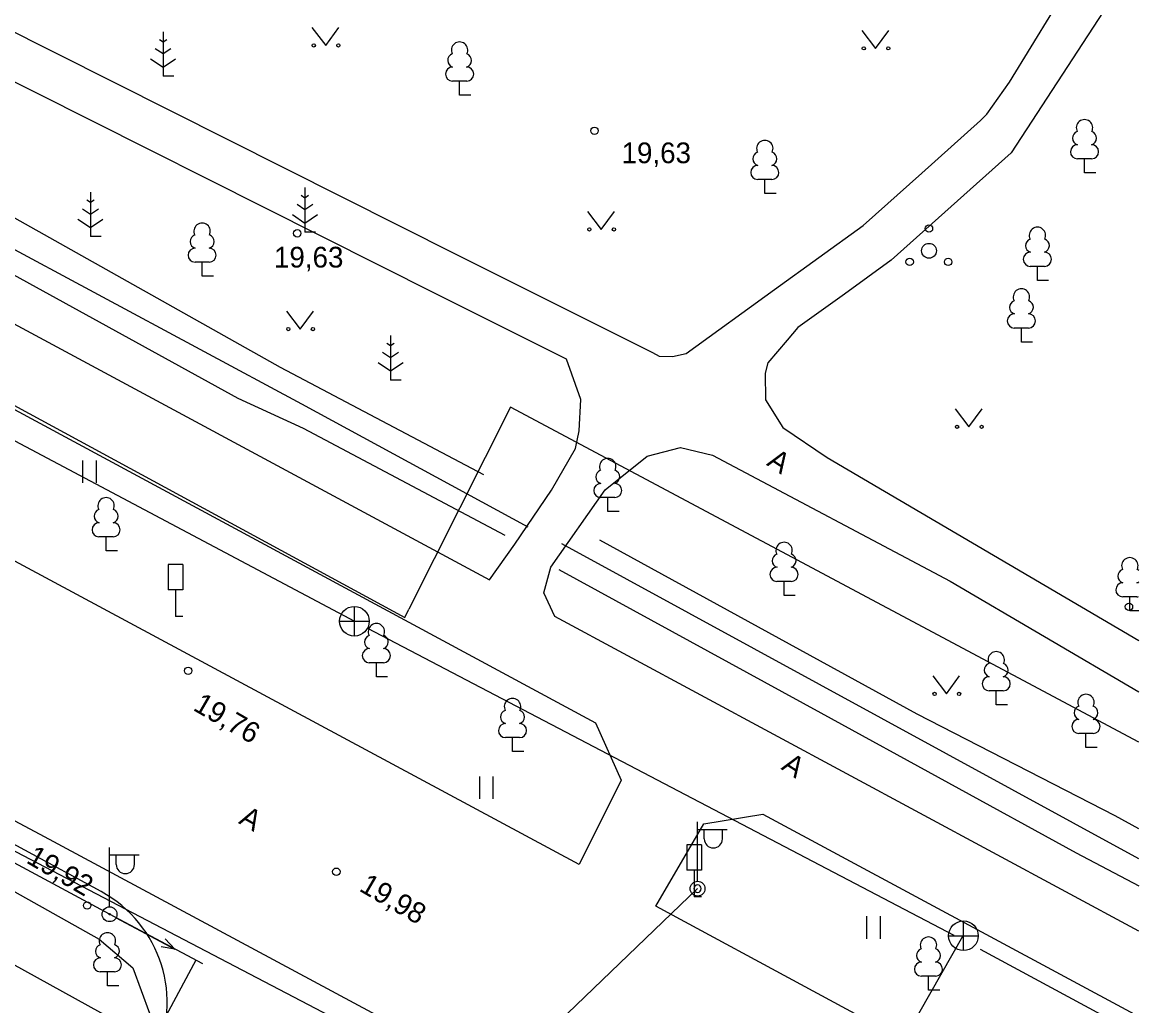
# Model space of a CAD drawing. Extents: x 713497 to 713863, y 6590062 to 6590327.
# Drawn here: x 713825.68 to 713863.36, y 6590124.29 to 6590157.47 of the extents above; entities that cross this region are included whole.
import ezdxf

# ---------------------------------------------------------------- set-up
doc = ezdxf.new("R2010")
doc.units = 0
for name, color, linetype in [('AED', 7, 'Continuous'), ('HALJASTUS', 7, 'Continuous'), ('HOONE', 7, 'Continuous'), ('KKAEV', 7, 'Continuous'), ('KORGUS', 7, 'Continuous'), ('KTRASS', 7, 'Continuous'), ('LIIKLUS', 7, 'Continuous'), ('MPKAABEL', 7, 'Continuous'), ('MPOHULIIN', 7, 'Continuous'), ('POST', 7, 'Continuous'), ('PUU', 7, 'Continuous'), ('SITRASS', 7, 'Continuous'), ('TEE', 7, 'Continuous'), ('TTRASS', 7, 'Continuous'), ('VTRASS', 7, 'Continuous')]:
    doc.layers.add(name, color=color, linetype=linetype)

msp = doc.modelspace()

# ---------------------------------------------------------------- linework, layer by layer
at = {"layer": 'AED'}
for points in [[(713842.75, 6590140.44), (713835.11, 6590144.59), (713824.81, 6590150.12), (713803.9, 6590161.43), (713731.96, 6590199.96)], [(713863.358, 6590129.245), (713843.89, 6590139.87)]]:
    msp.add_lwpolyline(points, dxfattribs=at)
at = {"layer": 'HALJASTUS'}
for p, q in [((713835.457, 6590157.297), (713835.92, 6590156.69)), ((713835.92, 6590156.69), (713836.366, 6590157.297)), ((713854.017, 6590157.197), (713854.48, 6590156.59)), ((713854.48, 6590156.59), (713854.926, 6590157.197)), ((713844.757, 6590151.087), (713845.22, 6590150.48)), ((713845.22, 6590150.48), (713845.666, 6590151.087)), ((713834.597, 6590147.727), (713835.06, 6590147.12)), ((713835.06, 6590147.12), (713835.506, 6590147.727)), ((713857.167, 6590144.427), (713857.63, 6590143.82)), ((713857.63, 6590143.82), (713858.076, 6590144.427)), ((713827.715, 6590142.688), (713827.715, 6590141.927)), ((713828.17, 6590142.688), (713828.17, 6590141.927)), ((713856.407, 6590135.417), (713856.87, 6590134.81)), ((713856.87, 6590134.81), (713857.316, 6590135.417)), ((713841.11, 6590132.026), (713841.11, 6590131.264)), ((713841.565, 6590132.026), (713841.565, 6590131.264)), ((713854.176, 6590127.307), (713854.176, 6590126.546)), ((713854.631, 6590127.307), (713854.631, 6590126.546))]:
    msp.add_line(p, q, dxfattribs=at)
for points in [[(713841.26, 6590142.2), (713834.39, 6590145.82), (713823.52, 6590151.93), (713808.23, 6590160.2), (713806.22, 6590161.53), (713798.4, 6590165.35), (713781.9, 6590174.22), (713774.18, 6590178.32), (713771.41, 6590180.04), (713767.95, 6590181.54), (713761.08, 6590185.35), (713755.64, 6590188.21), (713751.36, 6590190.34), (713748.73, 6590191.96), (713741.58, 6590196.11), (713734, 6590200.4)], [(713732.19, 6590199.21), (713738.7, 6590195.69), (713747.61, 6590190.82), (713767.02, 6590180.35), (713771.65, 6590178.11), (713786.98, 6590169.69), (713793.79, 6590166.16), (713813.16, 6590155.69), (713817.55, 6590153.26), (713832.96, 6590144.79), (713835.16, 6590143.78), (713841.97, 6590140.16)], [(713863.358, 6590130.259), (713862.56, 6590130.7), (713855.88, 6590134.13), (713845.17, 6590140)], [(713843.79, 6590139.01), (713852.63, 6590134.17), (713861.25, 6590129.45), (713863.358, 6590128.329)]]:
    msp.add_lwpolyline(points, dxfattribs=at)
for centre, radius in [((713835.519, 6590156.69), 0.055), ((713836.348, 6590156.69), 0.055), ((713854.079, 6590156.59), 0.055), ((713854.908, 6590156.59), 0.055), ((713844.819, 6590150.48), 0.055), ((713845.648, 6590150.48), 0.055), ((713856.28, 6590150.51), 0.125), ((713856.28, 6590149.76), 0.25), ((713855.63, 6590149.385), 0.125), ((713856.93, 6590149.385), 0.125), ((713834.659, 6590147.12), 0.055), ((713835.488, 6590147.12), 0.055), ((713857.229, 6590143.82), 0.055), ((713858.058, 6590143.82), 0.055), ((713856.469, 6590134.81), 0.055), ((713857.298, 6590134.81), 0.055)]:
    msp.add_circle(centre, radius, dxfattribs=at)
at = {"layer": 'HOONE'}
msp.add_lwpolyline([(713734.713, 6590179.152), (713785.66, 6590151.72), (713826.27, 6590130.08), (713863.358, 6590110.159)], dxfattribs=at)
at = {"layer": 'KKAEV'}
for p, q in [((713836.888, 6590136.76), (713836.888, 6590137.76)), ((713836.388, 6590137.26), (713837.388, 6590137.26)), ((713857.445, 6590126.148), (713857.445, 6590127.148)), ((713856.945, 6590126.648), (713857.945, 6590126.648))]:
    msp.add_line(p, q, dxfattribs=at)
for centre in [(713836.888, 6590137.26), (713857.445, 6590126.648)]:
    msp.add_circle(centre, 0.5, dxfattribs=at)
at = {"layer": 'KORGUS'}
for centre in [(713844.99, 6590153.81), (713834.96, 6590150.35), (713863.03, 6590137.75), (713831.28, 6590135.59), (713836.28, 6590128.81), (713827.87, 6590127.67)]:
    msp.add_circle(centre, 0.125, dxfattribs=at)
at = {"layer": 'KTRASS'}
for points in [[(713813.595, 6590149.622), (713836.888, 6590137.26)], [(713837.331, 6590137.028), (713857.122, 6590126.667)], [(713859.576, 6590106.384), (713849.065, 6590111.945), (713857.429, 6590126.632)], [(713858.005, 6590126.198), (713863.358, 6590123.311)]]:
    msp.add_lwpolyline(points, dxfattribs=at)
at = {"layer": 'LIIKLUS'}
for points in [[(713830.604, 6590139.171), (713830.604, 6590138.321)], [(713831.104, 6590139.171), (713830.604, 6590139.171)], [(713831.104, 6590139.171), (713831.104, 6590138.321)], [(713831.104, 6590138.321), (713830.604, 6590138.321)], [(713830.854, 6590138.321), (713830.854, 6590137.421)], [(713831.104, 6590137.421), (713830.854, 6590137.421)], [(713848.108, 6590129.712), (713848.108, 6590128.862)], [(713848.608, 6590129.712), (713848.108, 6590129.712)], [(713848.608, 6590129.712), (713848.608, 6590128.862)], [(713848.608, 6590128.862), (713848.108, 6590128.862)], [(713848.358, 6590128.862), (713848.358, 6590127.962)], [(713848.608, 6590127.962), (713848.358, 6590127.962)]]:
    msp.add_lwpolyline(points, dxfattribs=at)
at = {"layer": 'MPKAABEL'}
for points in [[(713831.772, 6590125.699), (713828.625, 6590127.375), (713802.947, 6590141.184), (713775.431, 6590155.836), (713748.262, 6590170.579), (713743.764, 6590161.693), (713741.527, 6590162.242)], [(713769.832, 6590143.392), (713772.837, 6590149.111), (713775.904, 6590154.621), (713783.15, 6590150.665), (713792.756, 6590145.834), (713802.454, 6590140.499), (713816.774, 6590132.975), (713828.273, 6590126.537), (713829.411, 6590125.567), (713830.253, 6590123.272), (713831.773, 6590121.257), (713837.66, 6590119.057), (713843.1, 6590118.531), (713851.23, 6590114.43), (713852.8, 6590114.122), (713856.379, 6590111.655), (713863.358, 6590107.953)], [(713848.471, 6590128.239), (713839.678, 6590119.797), (713843.412, 6590119.073), (713856.788, 6590112.375)], [(713831.539, 6590125.823), (713812.157, 6590089.684), (713797.659, 6590062.302)]]:
    msp.add_lwpolyline(points, dxfattribs=at)
at = {"layer": 'MPOHULIIN'}
for p, q in [((713828.845, 6590127.258), (713830.831, 6590126.2)), ((713830.831, 6590126.2), (713830.504, 6590126.545)), ((713830.831, 6590126.2), (713830.363, 6590126.281))]:
    msp.add_line(p, q, dxfattribs=at)
at = {"layer": 'POST'}
for p, q in [((713848.471, 6590128.489), (713848.471, 6590130.489)), ((713848.471, 6590130.239), (713849.471, 6590130.239)), ((713848.697, 6590129.918), (713848.697, 6590130.239)), ((713849.31, 6590129.918), (713849.31, 6590130.239)), ((713828.625, 6590127.625), (713828.625, 6590129.625)), ((713828.625, 6590129.375), (713829.625, 6590129.375)), ((713828.851, 6590129.054), (713828.851, 6590129.375)), ((713829.464, 6590129.054), (713829.464, 6590129.375))]:
    msp.add_line(p, q, dxfattribs=at)
for centre, radius in [((713848.471, 6590128.239), 0.25), ((713828.625, 6590127.375), 0.25), ((713828.625, 6590127.375), 0.0234)]:
    msp.add_circle(centre, radius, dxfattribs=at)
for centre, radius, start, end in [((713849.004, 6590129.918), 0.306, 180, 0), ((713829.158, 6590129.054), 0.306, 180, 0), ((713848.471, 6590128.239), 0.125, 0, 180), ((713848.471, 6590128.239), 0.125, 180, 0)]:
    msp.add_arc(centre, radius, start, end, dxfattribs=at)
at = {"layer": 'PUU'}
for p, q in [((713830.43, 6590156.8), (713830.306, 6590156.883)), ((713830.43, 6590157.15), (713830.43, 6590155.65)), ((713830.554, 6590156.883), (713830.43, 6590156.8)), ((713830.43, 6590156.4), (713830.163, 6590156.578)), ((713830.697, 6590156.578), (713830.43, 6590156.4)), ((713830.006, 6590156.239), (713830.43, 6590155.957)), ((713830.43, 6590155.957), (713830.854, 6590156.239)), ((713830.79, 6590155.65), (713830.43, 6590155.65)), ((713840.68, 6590155.485), (713840.2, 6590155.485)), ((713840.44, 6590155.01), (713840.44, 6590155.485)), ((713840.82, 6590155.01), (713840.44, 6590155.01)), ((713861.77, 6590152.865), (713861.29, 6590152.865)), ((713861.53, 6590152.39), (713861.53, 6590152.865)), ((713861.91, 6590152.39), (713861.53, 6590152.39)), ((713850.98, 6590152.165), (713850.5, 6590152.165)), ((713850.74, 6590151.69), (713850.74, 6590152.165)), ((713827.98, 6590151.74), (713827.98, 6590150.24)), ((713835.22, 6590151.54), (713835.096, 6590151.623)), ((713835.22, 6590151.89), (713835.22, 6590150.39)), ((713835.344, 6590151.623), (713835.22, 6590151.54)), ((713851.12, 6590151.69), (713850.74, 6590151.69)), ((713827.98, 6590151.39), (713827.856, 6590151.473)), ((713828.104, 6590151.473), (713827.98, 6590151.39)), ((713835.22, 6590151.14), (713834.953, 6590151.318)), ((713835.487, 6590151.318), (713835.22, 6590151.14)), ((713827.556, 6590150.829), (713827.98, 6590150.547)), ((713827.98, 6590150.99), (713827.713, 6590151.168)), ((713828.247, 6590151.168), (713827.98, 6590150.99)), ((713827.98, 6590150.547), (713828.404, 6590150.829)), ((713834.796, 6590150.979), (713835.22, 6590150.697)), ((713835.22, 6590150.697), (713835.644, 6590150.979)), ((713828.34, 6590150.24), (713827.98, 6590150.24)), ((713835.58, 6590150.39), (713835.22, 6590150.39)), ((713831.99, 6590149.375), (713831.51, 6590149.375)), ((713831.75, 6590148.9), (713831.75, 6590149.375)), ((713860.18, 6590149.235), (713859.7, 6590149.235)), ((713859.94, 6590148.76), (713859.94, 6590149.235)), ((713832.13, 6590148.9), (713831.75, 6590148.9)), ((713860.32, 6590148.76), (713859.94, 6590148.76)), ((713859.64, 6590147.155), (713859.16, 6590147.155)), ((713859.4, 6590146.68), (713859.4, 6590147.155)), ((713838.11, 6590146.9), (713838.11, 6590145.4)), ((713859.78, 6590146.68), (713859.4, 6590146.68)), ((713838.11, 6590146.15), (713837.843, 6590146.328)), ((713838.11, 6590146.55), (713837.986, 6590146.633)), ((713838.234, 6590146.633), (713838.11, 6590146.55)), ((713838.377, 6590146.328), (713838.11, 6590146.15)), ((713837.686, 6590145.989), (713838.11, 6590145.707)), ((713838.11, 6590145.707), (713838.534, 6590145.989)), ((713838.47, 6590145.4), (713838.11, 6590145.4)), ((713845.68, 6590141.435), (713845.2, 6590141.435)), ((713845.44, 6590140.96), (713845.44, 6590141.435)), ((713845.82, 6590140.96), (713845.44, 6590140.96)), ((713828.749, 6590140.11), (713828.269, 6590140.11)), ((713828.509, 6590139.635), (713828.509, 6590140.11)), ((713828.889, 6590139.635), (713828.509, 6590139.635)), ((713851.63, 6590138.605), (713851.15, 6590138.605)), ((713851.39, 6590138.13), (713851.39, 6590138.605)), ((713851.77, 6590138.13), (713851.39, 6590138.13)), ((713863.3, 6590138.085), (713862.82, 6590138.085)), ((713863.06, 6590137.61), (713863.06, 6590138.085)), ((713863.358, 6590137.61), (713863.06, 6590137.61)), ((713837.871, 6590135.862), (713837.391, 6590135.862)), ((713837.631, 6590135.387), (713837.631, 6590135.862)), ((713838.011, 6590135.387), (713837.631, 6590135.387)), ((713858.79, 6590134.915), (713858.31, 6590134.915)), ((713858.55, 6590134.44), (713858.55, 6590134.915)), ((713858.93, 6590134.44), (713858.55, 6590134.44)), ((713861.82, 6590133.475), (713861.34, 6590133.475)), ((713861.58, 6590133), (713861.58, 6590133.475)), ((713842.466, 6590133.336), (713841.986, 6590133.336)), ((713842.226, 6590132.861), (713842.226, 6590133.336)), ((713842.606, 6590132.861), (713842.226, 6590132.861)), ((713861.96, 6590133), (713861.58, 6590133)), ((713828.794, 6590125.431), (713828.314, 6590125.431)), ((713828.554, 6590124.956), (713828.554, 6590125.431)), ((713856.504, 6590125.286), (713856.024, 6590125.286)), ((713856.264, 6590124.811), (713856.264, 6590125.286)), ((713828.934, 6590124.956), (713828.554, 6590124.956)), ((713856.644, 6590124.811), (713856.264, 6590124.811))]:
    msp.add_line(p, q, dxfattribs=at)
for centre, radius, start, end in [((713840.44, 6590156.53), 0.277, 332.5799, 207.4201), ((713840.27, 6590156.183), 0.233, 109.0217, 253.1415), ((713840.61, 6590156.183), 0.233, 286.8508, 70.9859), ((713840.203, 6590155.722), 0.238, 90.0016, 269.3953), ((713840.677, 6590155.722), 0.238, 270.6047, 89.9984), ((713861.53, 6590153.91), 0.277, 332.5799, 207.4201), ((713850.74, 6590153.21), 0.277, 332.5799, 207.4201), ((713861.36, 6590153.563), 0.233, 109.0217, 253.1415), ((713861.7, 6590153.563), 0.233, 286.8508, 70.9859), ((713850.57, 6590152.863), 0.233, 109.0217, 253.1415), ((713850.91, 6590152.863), 0.233, 286.8508, 70.9859), ((713861.293, 6590153.102), 0.238, 90.0016, 269.3953), ((713861.767, 6590153.102), 0.238, 270.6047, 89.9984), ((713850.503, 6590152.402), 0.238, 90.0016, 269.3953), ((713850.977, 6590152.402), 0.238, 270.6047, 89.9984), ((713831.75, 6590150.42), 0.277, 332.5799, 207.4201), ((713859.94, 6590150.28), 0.277, 332.5799, 207.4201), ((713831.58, 6590150.073), 0.233, 109.0217, 253.1415), ((713831.92, 6590150.073), 0.233, 286.8508, 70.9859), ((713859.77, 6590149.933), 0.233, 109.0217, 253.1415), ((713860.11, 6590149.933), 0.233, 286.8508, 70.9859), ((713831.513, 6590149.612), 0.238, 90.0016, 269.3953), ((713831.987, 6590149.612), 0.238, 270.6047, 89.9984), ((713859.703, 6590149.472), 0.238, 90.0016, 269.3953), ((713860.177, 6590149.472), 0.238, 270.6047, 89.9984), ((713859.4, 6590148.2), 0.277, 332.5799, 207.4201), ((713859.23, 6590147.853), 0.233, 109.0217, 253.1415), ((713859.57, 6590147.853), 0.233, 286.8508, 70.9859), ((713859.163, 6590147.392), 0.238, 90.0016, 269.3953), ((713859.637, 6590147.392), 0.238, 270.6047, 89.9984), ((713845.44, 6590142.48), 0.277, 332.5799, 207.4201), ((713845.27, 6590142.133), 0.233, 109.0217, 253.1415), ((713845.61, 6590142.133), 0.233, 286.8508, 70.9859), ((713845.203, 6590141.672), 0.238, 90.0016, 269.3953), ((713845.677, 6590141.672), 0.238, 270.6047, 89.9984), ((713828.509, 6590141.155), 0.277, 332.5799, 207.4201), ((713828.339, 6590140.807), 0.233, 109.0217, 253.1415), ((713828.68, 6590140.807), 0.233, 286.8508, 70.9859), ((713828.272, 6590140.347), 0.238, 90.0016, 269.3953), ((713828.747, 6590140.347), 0.238, 270.6047, 89.9984), ((713851.39, 6590139.65), 0.277, 332.5799, 207.4201), ((713851.22, 6590139.303), 0.233, 109.0217, 253.1415), ((713851.56, 6590139.303), 0.233, 286.8508, 70.9859), ((713863.06, 6590139.13), 0.277, 332.5799, 207.4201), ((713851.153, 6590138.842), 0.238, 90.0016, 269.3953), ((713851.627, 6590138.842), 0.238, 270.6047, 89.9984), ((713862.89, 6590138.783), 0.233, 109.0217, 253.1415), ((713863.23, 6590138.783), 0.233, 56.6646, 70.9859), ((713862.823, 6590138.322), 0.238, 90.0016, 269.3953), ((713863.23, 6590138.783), 0.233, 286.8508, 303.3354), ((713863.297, 6590138.322), 0.238, 75.269, 89.9984), ((713863.297, 6590138.322), 0.238, 270.6047, 284.731), ((713837.631, 6590136.907), 0.277, 332.5799, 207.4201), ((713837.461, 6590136.56), 0.233, 109.0217, 253.1415), ((713837.801, 6590136.56), 0.233, 286.8508, 70.9859), ((713837.394, 6590136.099), 0.238, 90.0016, 269.3953), ((713837.869, 6590136.099), 0.238, 270.6047, 89.9984), ((713858.55, 6590135.96), 0.277, 332.5799, 207.4201), ((713858.38, 6590135.613), 0.233, 109.0217, 253.1415), ((713858.72, 6590135.613), 0.233, 286.8508, 70.9859), ((713858.313, 6590135.152), 0.238, 90.0016, 269.3953), ((713858.787, 6590135.152), 0.238, 270.6047, 89.9984), ((713842.226, 6590134.381), 0.277, 332.5799, 207.4201), ((713861.58, 6590134.52), 0.277, 332.5799, 207.4201), ((713842.056, 6590134.033), 0.233, 109.0217, 253.1415), ((713842.396, 6590134.033), 0.233, 286.8508, 70.9859), ((713861.41, 6590134.173), 0.233, 109.0217, 253.1415), ((713861.75, 6590134.173), 0.233, 286.8508, 70.9859), ((713861.343, 6590133.712), 0.238, 90.0016, 269.3953), ((713861.817, 6590133.712), 0.238, 270.6047, 89.9984), ((713841.989, 6590133.573), 0.238, 90.0016, 269.3953), ((713842.464, 6590133.573), 0.238, 270.6047, 89.9984), ((713828.554, 6590126.476), 0.277, 332.5799, 207.4201), ((713828.384, 6590126.128), 0.233, 109.0217, 253.1415), ((713828.724, 6590126.128), 0.233, 286.8508, 70.9859), ((713856.264, 6590126.331), 0.277, 332.5799, 207.4201), ((713856.094, 6590125.984), 0.233, 109.0217, 253.1415), ((713856.434, 6590125.984), 0.233, 286.8508, 70.9859), ((713828.317, 6590125.668), 0.238, 90.0016, 269.3953), ((713828.792, 6590125.668), 0.238, 270.6047, 89.9984), ((713856.026, 6590125.524), 0.238, 90.0016, 269.3953), ((713856.501, 6590125.524), 0.238, 270.6047, 89.9984)]:
    msp.add_arc(centre, radius, start, end, dxfattribs=at)
at = {"layer": 'SITRASS'}
msp.add_lwpolyline([(713863.358, 6590109.383), (713837.06, 6590123.42), (713818.31, 6590133.22), (713795.51, 6590145.62), (713774.46, 6590157.04), (713767.746, 6590144.461), (713761.9, 6590133.51)], dxfattribs=at)
at = {"layer": 'TEE'}
for points in [[(713844.05, 6590146.1), (713839.66, 6590148.3), (713822.24, 6590157.05), (713808.23, 6590164.82), (713794.22, 6590172.59), (713772.5, 6590184.62), (713759.78, 6590192.031), (713751.212, 6590196.696), (713745.898, 6590199.593), (713737.505, 6590202.852), (713737.134, 6590202.824), (713736.264, 6590202.76), (713735.329, 6590202.691), (713734.382, 6590202.621), (713732.876, 6590202.51)], [(713731.142, 6590198.62), (713786.08, 6590168.47), (713841.45, 6590138.66), (713842.3, 6590139.86), (713843.54, 6590141.68), (713844.35, 6590143.09), (713844.47, 6590143.68), (713844.53, 6590144.74), (713844.05, 6590146.1)], [(713729.503, 6590195.962), (713814.96, 6590150.045), (713845.029, 6590133.836), (713845.889, 6590131.902), (713844.472, 6590129.05), (713816.858, 6590143.891), (713797.519, 6590154.285), (713778.342, 6590164.655), (713757.415, 6590175.881), (713740.491, 6590185.02), (713731.812, 6590189.692)], [(713778.16, 6590187.46), (713777.37, 6590185.76), (713776.41, 6590184.22), (713783.74, 6590180.13), (713808.94, 6590166.14), (713822.94, 6590158.38), (713840.33, 6590149.64), (713846.95, 6590146.33), (713847.17, 6590146.21), (713847.63, 6590146.19), (713848.09, 6590146.29), (713851.07, 6590148.45), (713854.06, 6590150.61), (713856.04, 6590152.38), (713858.02, 6590154.16), (713858.23, 6590154.37), (713859, 6590155.45), (713860.46, 6590157.83), (713861.92, 6590160.21), (713863.06, 6590162.07), (713863.358, 6590162.46)], [(713828.341, 6590128.138), (713812.872, 6590136.509), (713793.453, 6590146.972), (713774.088, 6590157.345), (713753.397, 6590168.434), (713735.495, 6590177.892), (713731.587, 6590178.663), (713718.885, 6590185.577)], [(713863.358, 6590159.659), (713863.19, 6590159.42), (713859.05, 6590153.07), (713855, 6590149.44), (713853.43, 6590148.3), (713851.86, 6590147.17), (713851.49, 6590146.75), (713850.84, 6590145.98), (713850.75, 6590145.63), (713850.76, 6590144.73), (713851.35, 6590143.8), (713852.84, 6590142.79), (713863.358, 6590136.614)], [(713863.358, 6590126.8), (713843.65, 6590137.42), (713843.28, 6590138.22), (713843.52, 6590139.09), (713845.35, 6590141.69), (713846.77, 6590142.83), (713847.9, 6590143.12), (713848.98, 6590142.87), (713857, 6590138.61), (713863.358, 6590134.879)], [(713863.358, 6590118.862), (713857.979, 6590121.753), (713847.06, 6590127.652), (713848.682, 6590130.431), (713850.677, 6590130.747), (713863.358, 6590123.929)]]:
    msp.add_lwpolyline(points, dxfattribs=at)
msp.add_arc((713826.317, 6590124.396), 4.254, 333.3387, 61.581, dxfattribs=at)
at = {"layer": 'TTRASS'}
for points in [[(713764.762, 6590177.546), (713819.5, 6590147.74), (713838.59, 6590137.39), (713838.728, 6590137.664)], [(713863.358, 6590133.183), (713842.16, 6590144.48), (713838.728, 6590137.664)]]:
    msp.add_lwpolyline(points, dxfattribs=at)
at = {"layer": 'VTRASS'}
msp.add_lwpolyline([(713863.358, 6590105.24), (713853.675, 6590110.345), (713840.649, 6590117.222), (713835.698, 6590119.976), (713821.055, 6590128.059), (713815.868, 6590130.724), (713800.871, 6590138.437), (713785.173, 6590146.474), (713766.203, 6590156.055), (713754.925, 6590161.75), (713749.339, 6590164.472)], dxfattribs=at)

# ---------------------------------------------------------------- texts
at = {"layer": 'KORGUS'}
for p in [(713845.906, 6590152.715), (713834.176, 6590149.195)]:
    msp.add_text('19,63', height=0.7, dxfattribs=at).set_placement(p)
for s, p in [('19,76', (713831.409, 6590134.281)), ('19,92', (713825.78, 6590129.132)), ('19,98', (713837.016, 6590128.183))]:
    msp.add_text(s, height=0.7, rotation=329.8372, dxfattribs=at).set_placement(p)
at = {"layer": 'TEE'}
for rotation, p in [(327.1011, (713850.772, 6590142.543)), (327.1011, (713851.262, 6590132.283)), (330.6972, (713832.953, 6590130.456))]:
    msp.add_text('A', height=0.7, rotation=rotation, dxfattribs=at).set_placement(p)

doc.saveas('drawing.dxf')
